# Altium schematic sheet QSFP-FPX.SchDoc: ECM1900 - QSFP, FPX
size C; Organization: Opal Kelly; Address1: 13500 SW 72nd Ave STE 100; Address3: Portland, OR  97223; Address4: http://www.opalkelly.com; DocumentNumber: xxx; Revision: 1; SheetNumber: 9; SheetTotal: 12; PageSetup: Record=PageOptions¦CenterHorizontal=True¦CenterVertical=True¦PrintScale=0.52¦XCorrection=1.00¦YCorrection=1.00¦PrintKind=0¦BorderSize=5000000¦LeftOffset=0¦BottomOffset=0¦Orientation=2¦PaperLength=1000¦PaperWidth=1000¦Scale=100¦PaperSource=7¦PrintQuality=-4¦MediaType=1¦DitherType=10¦PaperKind=Letter¦PrintScaleMode=1
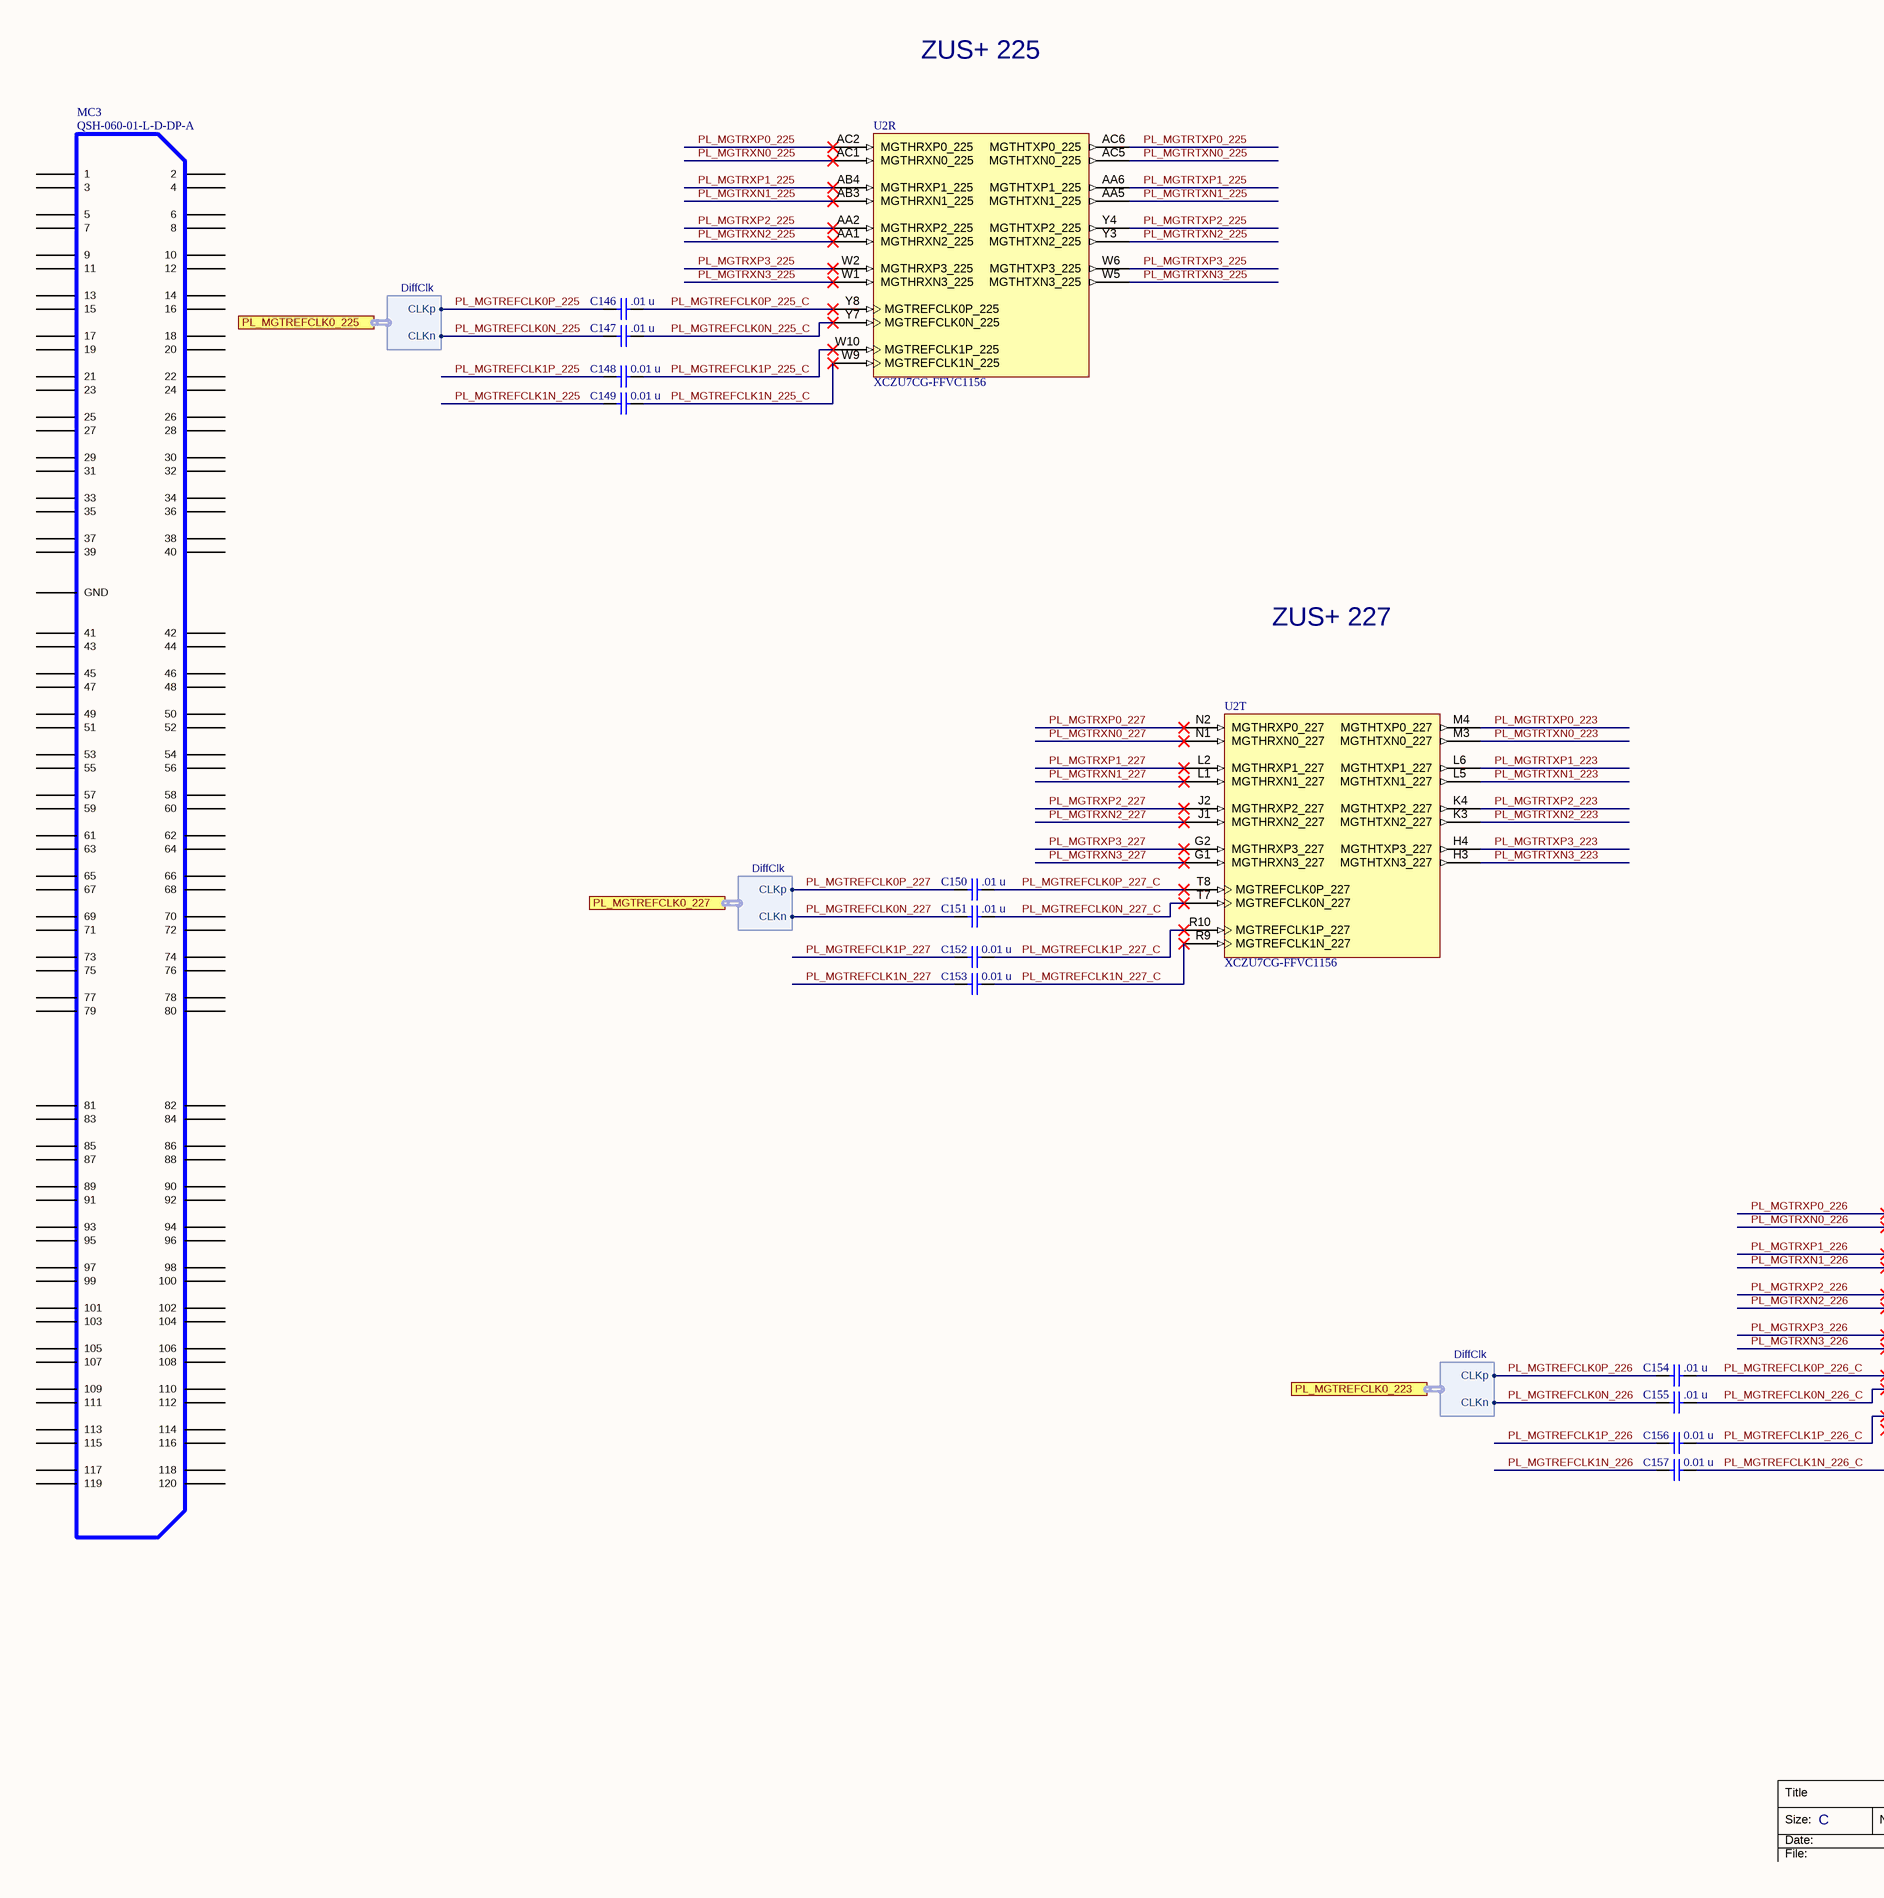
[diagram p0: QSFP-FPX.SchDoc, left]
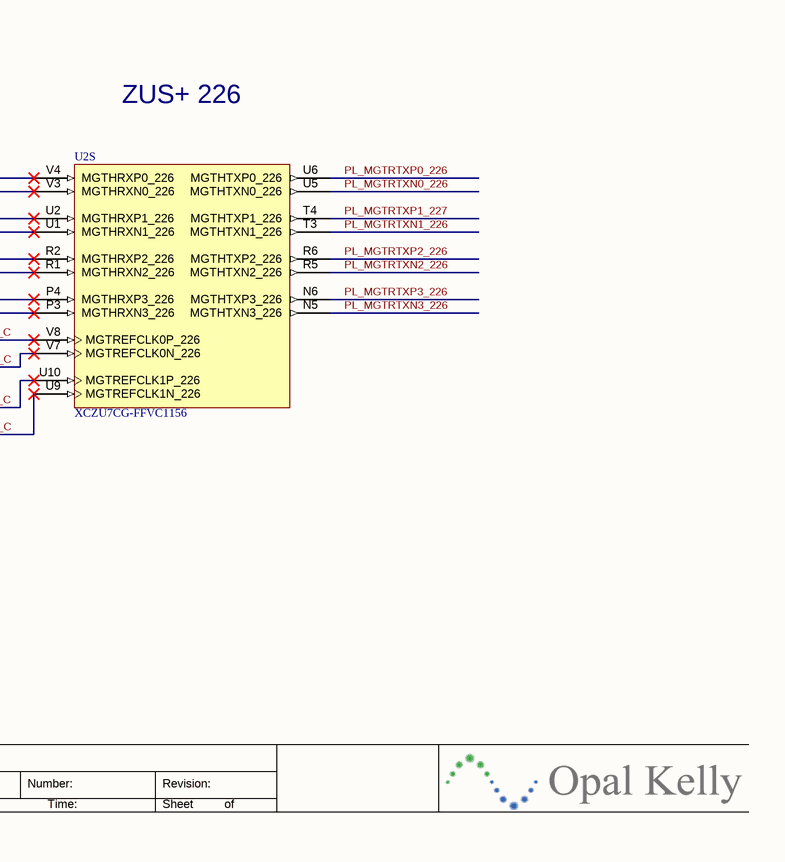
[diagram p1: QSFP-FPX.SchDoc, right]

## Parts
C146  value .01 u  [CAPC0603X03A]  (hidden comment: C0603X5R1A103K030BA)
C147  value .01 u  [CAPC0603X03A]  (hidden comment: C0603X5R1A103K030BA)
C148  value 0.01 u  [CAPC1005X06A]  (hidden comment: SM-0402, 10%, 16V, X5R)
C149  value 0.01 u  [CAPC1005X06A]  (hidden comment: SM-0402, 10%, 16V, X5R)
C150  value .01 u  [CAPC0603X03A]  (hidden comment: C0603X5R1A103K030BA)
C151  value .01 u  [CAPC0603X03A]  (hidden comment: C0603X5R1A103K030BA)
C152  value 0.01 u  [CAPC1005X06A]  (hidden comment: SM-0402, 10%, 16V, X5R)
C153  value 0.01 u  [CAPC1005X06A]  (hidden comment: SM-0402, 10%, 16V, X5R)
C154  value .01 u  [CAPC0603X03A]  (hidden comment: C0603X5R1A103K030BA)
C155  value .01 u  [CAPC0603X03A]  (hidden comment: C0603X5R1A103K030BA)
C156  value 0.01 u  [CAPC1005X06A]  (hidden comment: SM-0402, 10%, 16V, X5R)
C157  value 0.01 u  [CAPC1005X06A]  (hidden comment: SM-0402, 10%, 16V, X5R)
MC3  QSH-060-01-L-D-DP-A  [QSH-060-01-X-D-DP-A]
U2  XCZU7CG-FFVC1156  (parts R,S,T of 28)

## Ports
PL_MGTREFCLK0_223 (harness DiffClk), PL_MGTREFCLK0_225 (harness DiffClk), PL_MGTREFCLK0_227 (harness DiffClk)

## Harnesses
DiffClk: CLKp, CLKn

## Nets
PL_MGTREFCLK0N_225: C147.1 ; port PL_MGTREFCLK0_225.CLKn
PL_MGTREFCLK0N_225_C: C147.2 U2.Y7(MGTREFCLK0N_225)
PL_MGTREFCLK0N_226: C155.1 ; port PL_MGTREFCLK0_223.CLKn
PL_MGTREFCLK0N_226_C: C155.2 U2.V7(MGTREFCLK0N_226)
PL_MGTREFCLK0N_227: C151.1 ; port PL_MGTREFCLK0_227.CLKn
PL_MGTREFCLK0N_227_C: C151.2 U2.T7(MGTREFCLK0N_227)
PL_MGTREFCLK0P_225: C146.1 ; port PL_MGTREFCLK0_225.CLKp
PL_MGTREFCLK0P_225_C: C146.2 U2.Y8(MGTREFCLK0P_225)
PL_MGTREFCLK0P_226: C154.1 ; port PL_MGTREFCLK0_223.CLKp
PL_MGTREFCLK0P_226_C: C154.2 U2.V8(MGTREFCLK0P_226)
PL_MGTREFCLK0P_227: C150.1 ; port PL_MGTREFCLK0_227.CLKp
PL_MGTREFCLK0P_227_C: C150.2 U2.T8(MGTREFCLK0P_227)
PL_MGTREFCLK1N_225: C149.1
PL_MGTREFCLK1N_225_C: C149.2 U2.W9(MGTREFCLK1N_225)
PL_MGTREFCLK1N_226: C157.1
PL_MGTREFCLK1N_226_C: C157.2 U2.U9(MGTREFCLK1N_226)
PL_MGTREFCLK1N_227: C153.1
PL_MGTREFCLK1N_227_C: C153.2 U2.R9(MGTREFCLK1N_227)
PL_MGTREFCLK1P_225: C148.1
PL_MGTREFCLK1P_225_C: C148.2 U2.W10(MGTREFCLK1P_225)
PL_MGTREFCLK1P_226: C156.1
PL_MGTREFCLK1P_226_C: C156.2 U2.U10(MGTREFCLK1P_226)
PL_MGTREFCLK1P_227: C152.1
PL_MGTREFCLK1P_227_C: C152.2 U2.R10(MGTREFCLK1P_227)
PL_MGTRTXN0_223: U2.M3(MGTHTXN0_227)
PL_MGTRTXN0_225: U2.AC5(MGTHTXN0_225)
PL_MGTRTXN0_226: U2.U5(MGTHTXN0_226)
PL_MGTRTXN1_223: U2.L5(MGTHTXN1_227)
PL_MGTRTXN1_225: U2.AA5(MGTHTXN1_225)
PL_MGTRTXN1_226: U2.T3(MGTHTXN1_226)
PL_MGTRTXN2_223: U2.K3(MGTHTXN2_227)
PL_MGTRTXN2_225: U2.Y3(MGTHTXN2_225)
PL_MGTRTXN2_226: U2.R5(MGTHTXN2_226)
PL_MGTRTXN3_223: U2.H3(MGTHTXN3_227)
PL_MGTRTXN3_225: U2.W5(MGTHTXN3_225)
PL_MGTRTXN3_226: U2.N5(MGTHTXN3_226)
PL_MGTRTXP0_223: U2.M4(MGTHTXP0_227)
PL_MGTRTXP0_225: U2.AC6(MGTHTXP0_225)
PL_MGTRTXP0_226: U2.U6(MGTHTXP0_226)
PL_MGTRTXP1_223: U2.L6(MGTHTXP1_227)
PL_MGTRTXP1_225: U2.AA6(MGTHTXP1_225)
PL_MGTRTXP1_227: U2.T4(MGTHTXP1_226)
PL_MGTRTXP2_223: U2.K4(MGTHTXP2_227)
PL_MGTRTXP2_225: U2.Y4(MGTHTXP2_225)
PL_MGTRTXP2_226: U2.R6(MGTHTXP2_226)
PL_MGTRTXP3_223: U2.H4(MGTHTXP3_227)
PL_MGTRTXP3_225: U2.W6(MGTHTXP3_225)
PL_MGTRTXP3_226: U2.N6(MGTHTXP3_226)
PL_MGTRXN0_225: U2.AC1(MGTHRXN0_225)
PL_MGTRXN0_226: U2.V3(MGTHRXN0_226)
PL_MGTRXN0_227: U2.N1(MGTHRXN0_227)
PL_MGTRXN1_225: U2.AB3(MGTHRXN1_225)
PL_MGTRXN1_226: U2.U1(MGTHRXN1_226)
PL_MGTRXN1_227: U2.L1(MGTHRXN1_227)
PL_MGTRXN2_225: U2.AA1(MGTHRXN2_225)
PL_MGTRXN2_226: U2.R1(MGTHRXN2_226)
PL_MGTRXN2_227: U2.J1(MGTHRXN2_227)
PL_MGTRXN3_225: U2.W1(MGTHRXN3_225)
PL_MGTRXN3_226: U2.P3(MGTHRXN3_226)
PL_MGTRXN3_227: U2.G1(MGTHRXN3_227)
PL_MGTRXP0_225: U2.AC2(MGTHRXP0_225)
PL_MGTRXP0_226: U2.V4(MGTHRXP0_226)
PL_MGTRXP0_227: U2.N2(MGTHRXP0_227)
PL_MGTRXP1_225: U2.AB4(MGTHRXP1_225)
PL_MGTRXP1_226: U2.U2(MGTHRXP1_226)
PL_MGTRXP1_227: U2.L2(MGTHRXP1_227)
PL_MGTRXP2_225: U2.AA2(MGTHRXP2_225)
PL_MGTRXP2_226: U2.R2(MGTHRXP2_226)
PL_MGTRXP2_227: U2.J2(MGTHRXP2_227)
PL_MGTRXP3_225: U2.W2(MGTHRXP3_225)
PL_MGTRXP3_226: U2.P4(MGTHRXP3_226)
PL_MGTRXP3_227: U2.G2(MGTHRXP3_227)

Not connected (* = marked no-connect by the designer): MC3 0(GND) 1 2 3 4 5 6 7 8 9 10 11 12 13 14 15 16 17 18 19 20 21 22 23 24 25 26 27 28 29 30 31 32 33 34 35 36 37 38 39 40 41 42 43 44 45 46 47 48 49 50 51 52 53 54 55 56 57 58 59 60 61 62 63 64 65 66 67 68 69 70 71 72 73 74 75 76 77 78 79 80 81 82 83 84 85 86 87 88 89 90 91 92 93 94 95 96 97 98 99 100 101 102 103 104 105 106 107 108 109 110 111 112 113 114 115 116 117 118 119 120

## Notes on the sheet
- ZUS+ 225
- ZUS+ 227
- ZUS+ 226
- Title
- Size:
- Date:
- File:
- C
- Number:
- Time:
- Revision:
- Sheet
- of

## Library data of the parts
C146 C147 C150 C151 C154 C155 = 001180: Partnumber: 001180; manufacturer: TDK; ValueFloat: 1E-8; x_tolerance: 10
C148 C149 C152 C153 C156 C157 = 000295: Partnumber: 000295; manufacturer: Kemet; manufacturer_pn: C0402C103K4RACTU; ValueFloat: 1E-8; id: 1026; inventory_price: 0.0016; reorder_quantity: 30000; x_tolerance: 10
MC3 = QTH-DP_QSH-DP-060: 0.5mm Double Row High Speed Socket Assembly; manufacturer: Samtec; partnumber: 001699
U2 = XCZU7CG-FFVC1156: Zynq UltraScale+ FPGA; Manufacturer: Xilinx; Manufacturer_PN: XCZU7CG-1FFVC1156E; partnumber: 001836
